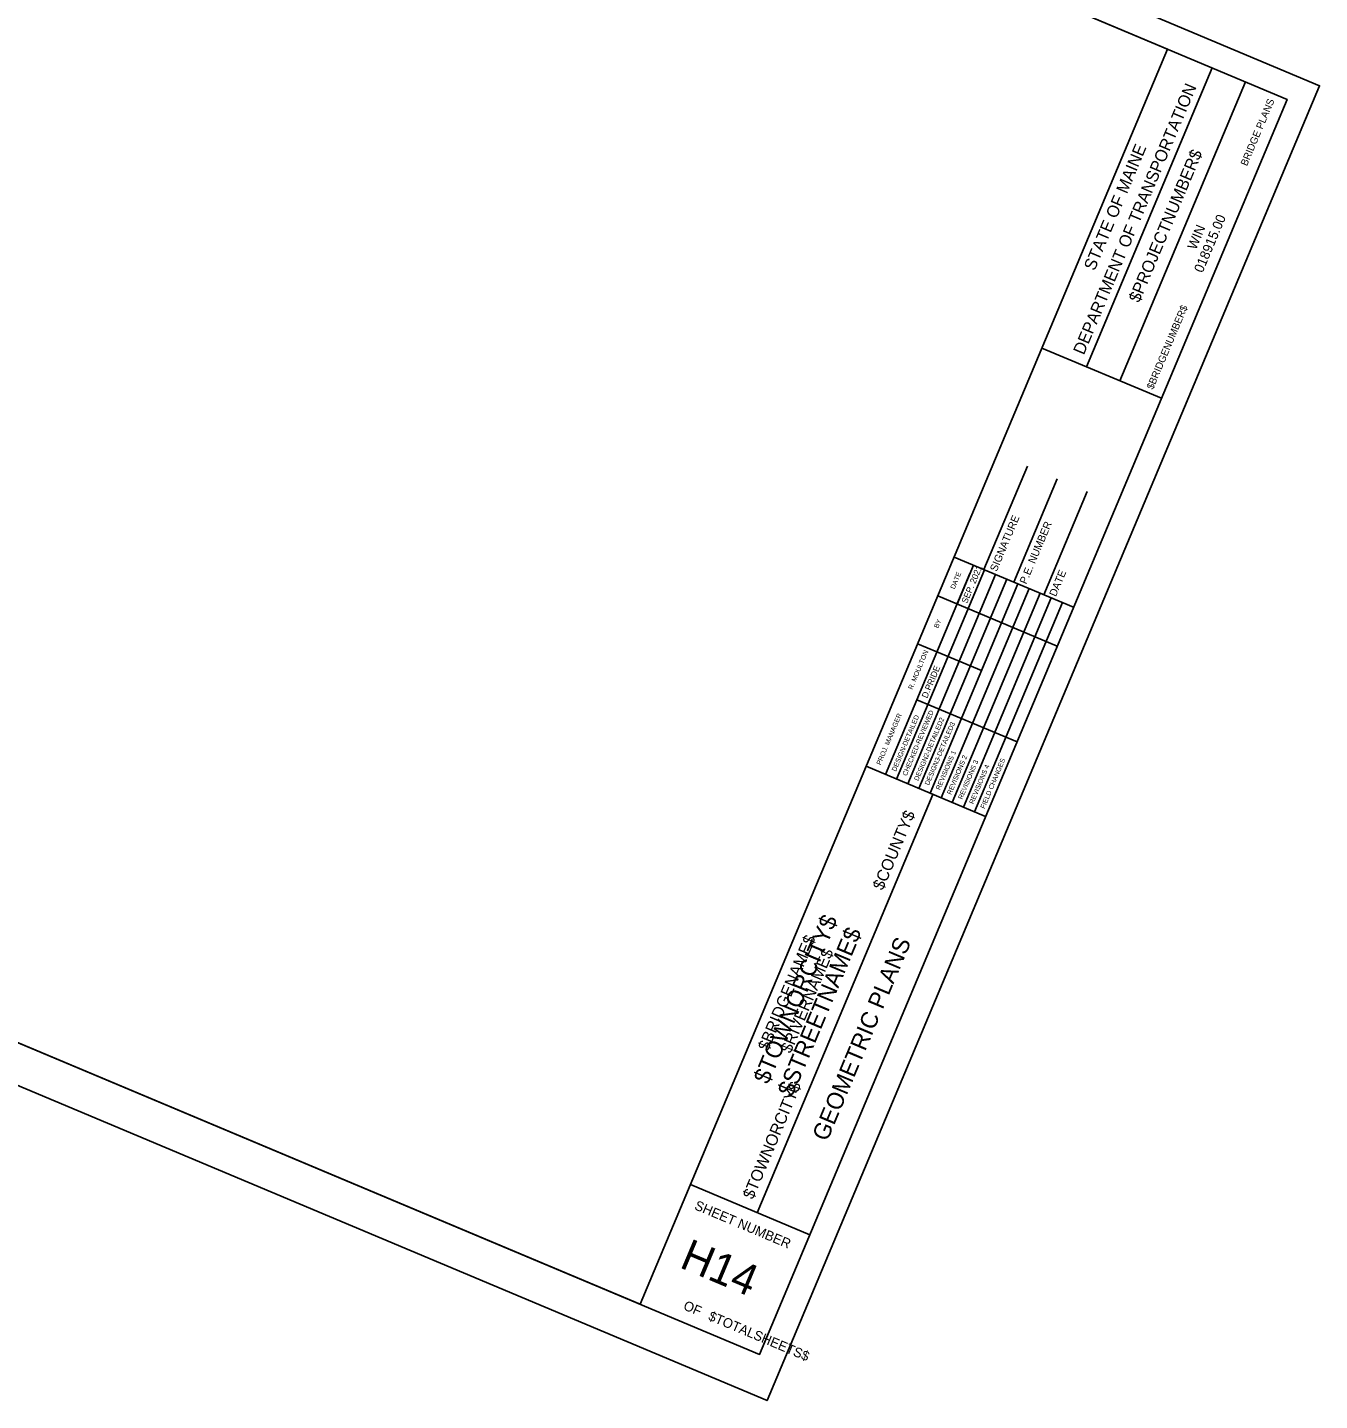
# Model space of a CAD drawing. Extents: x 1745429 to 1746425, y 462900 to 463737.
# Drawn here: x 1745927 to 1746425, y 462900 to 463430 of the extents above; entities that cross this region are included whole.
import ezdxf

# ---------------------------------------------------------------- set-up
doc = ezdxf.new("R2010")
doc.units = 0
for name, color, linetype in [('ANNOTATION', 7, 'Continuous'), ('D_Roadway_Centerline_Flags', 7, 'Continuous'), ('D_Roadway_Centerline_Text', 7, 'Continuous'), ('M_Fencing', 7, 'Continuous'), ('M_Misc_MiscItems', 7, 'Continuous')]:
    doc.layers.add(name, color=color, linetype=linetype)

msp = doc.modelspace()

# ---------------------------------------------------------------- linework, layer by layer
at = {"layer": 'D_Roadway_Centerline_Text'}
for p, q in [((1746163.2, 462937.51), (1746366.61, 463421.5)), ((1746335.36, 463299.03), (1746383.79, 463414.27)), ((1746348.24, 463293.61), (1746396.67, 463408.85)), ((1746318.17, 463306.24), (1746364.26, 463286.87)), ((1746295.8, 463220.77), (1746312.56, 463260.63)), ((1746307.33, 463215.93), (1746324.08, 463255.79)), ((1746318.85, 463211.08), (1746335.6, 463250.94)), ((1746284.28, 463225.61), (1746330.38, 463206.24)), ((1746250.38, 463144.95), (1746296.47, 463125.58)), ((1746208.35, 462972.78), (1746276.15, 463134.12)), ((1746182.58, 462983.62), (1746228.67, 462964.24))]:
    msp.add_line(p, q, dxfattribs=at)
msp.add_lwpolyline([(1745675.19, 463712.08), (1746412.7, 463402.13), (1746209.29, 462918.14), (1745471.78, 463228.09)], close=True, dxfattribs=at)
for points in [[(1746257.83, 463141.83), (1746290.36, 463219.23)], [(1746262.13, 463140.03), (1746296.02, 463220.68)], [(1746300.32, 463218.87), (1746266.42, 463138.22)], [(1746285.43, 463207.5), (1746291.72, 463222.48)], [(1746270.72, 463136.42), (1746304.61, 463217.07)], [(1746275.01, 463134.61), (1746308.91, 463215.26)], [(1746279.31, 463132.81), (1746313.2, 463213.46)], [(1746277.98, 463210.63), (1746324.08, 463191.26)], [(1746283.6, 463131), (1746317.5, 463211.65)], [(1746287.89, 463129.2), (1746321.79, 463209.85)], [(1746292.19, 463127.39), (1746326.08, 463208.04)], [(1746270.24, 463192.19), (1746277.68, 463189.06)], [(1746277.68, 463189.07), (1746294.86, 463181.85)], [(1746269.93, 463170.63), (1746308.58, 463154.38)]]:
    msp.add_lwpolyline(points, dxfattribs=at)
at = {"layer": 'M_Fencing'}
msp.add_lwpolyline([(1745428.55, 463229.67), (1746212.16, 462900.34), (1746425.25, 463407.38), (1745641.64, 463736.71)], close=True, dxfattribs=at)
at = {"layer": 'M_Misc_MiscItems'}
msp.add_lwpolyline([(1745675.19, 463712.08), (1746366.61, 463421.5), (1746163.2, 462937.51), (1745471.78, 463228.09)], close=True, dxfattribs=at)

# ---------------------------------------------------------------- texts
at = {"layer": 'ANNOTATION'}
for s, height, p in [('BRIDGE PLANS', 2.795, (1746397.24, 463376.22)), ('$BRIDGENUMBER$', 2.795, (1746361.03, 463290.05)), ('$COUNTY$', 4.536, (1746256.85, 463096.84)), ('$BRIDGENAME$', 4.5358, (1746212.59, 463034.83)), ('$RIVERNAME$', 4.5358, (1746221.32, 463033.95)), ('$TOWNORCITY$', 4.5358, (1746206.76, 462977.65))]:
    msp.add_text(s, height=height, rotation=67.2046, dxfattribs=at).set_placement(p)
at = {"layer": 'D_Roadway_Centerline_Flags'}
for s, p in [('$TOWNORCITY$', (1746212.66, 463022)), ('$STREETNAME$', (1746221.93, 463017.13))]:
    msp.add_text(s, height=6.5214, rotation=67.2046, dxfattribs=at).set_placement(p)
at = {"layer": 'D_Roadway_Centerline_Text'}
for s, height, rotation, p in [('DEPARTMENT OF TRANSPORTATION', 4.6588, 67.2046, (1746334.33, 463303.31)), ('STATE OF MAINE', 4.6588, 67.2046, (1746338.47, 463335.77)), ('$PROJECTNUMBER$', 4.6588, 67.2046, (1746355.73, 463323.45)), ('018915.00', 3.726, 67.2046, (1746380.12, 463335)), ('WIN', 3.726, 67.2046, (1746377.56, 463343.84)), ('SIGNATURE', 2.953, 67.2046, (1746300.7, 463219.76)), ('P.E. NUMBER', 2.9528, 67.2046, (1746312.13, 463214.95)), ('DATE', 1.857, 67.2046, (1746284.47, 463213.09)), ('SEP. 2021', 2.423, 67.2046, (1746289.26, 463207.49)), ('DATE', 2.953, 67.2046, (1746323.56, 463210.15)), ('BY', 1.857, 67.2046, (1746278.13, 463198.02)), ('R. MOULTON', 1.864, 67.2046, (1746268.19, 463174.36)), ('D.PRIDE', 2.423, 67.2046, (1746273.92, 463170.98)), ('CHECKED-REVIEWED', 1.8637, 67.2046, (1746265.99, 463141.03)), ('PROJ. MANAGER', 1.8637, 67.2046, (1746255.95, 463145.25)), ('DESIGN-DETAILED', 1.8637, 67.2046, (1746261.86, 463142.77)), ('DESIGN2-DETAILED2', 1.8637, 67.2046, (1746270.45, 463139.16)), ('DESIGN3-DETAILED3', 1.8637, 67.2046, (1746274.58, 463137.43)), ('REVISIONS 1', 1.8637, 67.2046, (1746278.87, 463135.62)), ('REVISIONS 2', 1.8637, 67.2046, (1746283.17, 463133.82)), ('REVISIONS 3', 1.8637, 67.2046, (1746287.46, 463132.01)), ('REVISIONS 4', 1.8637, 67.2046, (1746291.75, 463130.21)), ('FIELD CHANGES', 1.8637, 67.2046, (1746296.05, 463128.4)), ('GEOMETRIC PLANS', 6.5214, 67.2046, (1746235.35, 462999.95)), ('SHEET NUMBER', 3.7264, 337.2046, (1746183.86, 462974.2)), ('H14', 12.097, 337.2046, (1746177.96, 462951.82)), ('OF', 3.726, 337.2046, (1746179.57, 462935.58)), ('$TOTALSHEETS$', 3.7264, 337.2046, (1746189.2, 462931.53))]:
    msp.add_text(s, height=height, rotation=rotation, dxfattribs=at).set_placement(p)

doc.saveas('drawing.dxf')
